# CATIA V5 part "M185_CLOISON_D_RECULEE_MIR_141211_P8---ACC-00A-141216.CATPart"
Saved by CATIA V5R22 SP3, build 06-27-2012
Part number: Part3.1
Bounding box of the stored display mesh (mm): x -949.334 to -599.425, y 203.047 to 408.977, z -41.152 to 652.539
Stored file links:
  G:\trimise\M185_CLOISON_D_RECULEE_MIR_141211_P8---ACC-00A-141216.CATPart
  Y:\SICA\141120_P8\Mxxx_CLOISON_D_RECULEE_MIR_141210_P8.CATPart
  \\SERVANTES\Public\WORKERS\Costin\P8\work cloison\009-M185_CLOISON_D_AVANCEE_MIR_141211_P8---ACC-00A-141216.CATPart
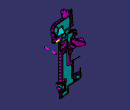
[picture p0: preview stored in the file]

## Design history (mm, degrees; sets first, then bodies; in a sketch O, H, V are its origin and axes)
StDynAnalysisRootNodeFeature1 "CATStDynAnalysisRootNodeName"
Set1 "Draft directions"
  Line1: stored without definition
  Line2: stored without definition
Body1 (main body)
Body2 "HARD_MATERIAL_ADVANCED"
  Solid1: solid without history
Body3 "Soft material advanced"
  Solid2: solid without history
